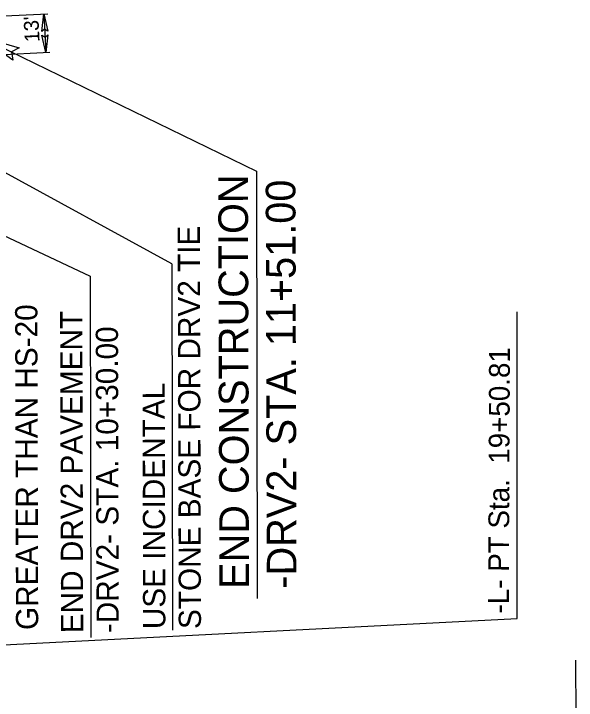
# Model space of a CAD drawing. Extents: x 1373164 to 1374172, y 550391 to 553180.
# Drawn here: x 1373885.8 to 1374075.4, y 551302.8 to 551534.2 of the extents above; entities that cross this region are included whole.
import ezdxf

# ---------------------------------------------------------------- set-up
doc = ezdxf.new("R2010")
doc.units = 0
for name, color, linetype in [('Exist Structure Major Deck Tunnel Box Culvert Cogo Point CELL', 7, 'Continuous'), ('Exist Structure Minor Pipes RCP 18 Inch Cogo Number', 7, 'Continuous'), ('Exist Utilities Sanitary Sewer Manhole Cogo Elevation', 7, 'Continuous')]:
    doc.layers.add(name, color=color, linetype=linetype)

msp = doc.modelspace()

# ---------------------------------------------------------------- linework, layer by layer
at = {"layer": 'Exist Structure Major Deck Tunnel Box Culvert Cogo Point CELL'}
for points in [[(1373895.24, 551528.26), (1373895.95, 551534.15), (1373897.29, 551528.33), (1373896.21, 551529.02)], [(1373885.47, 551518.53), (1373874.34, 551526.52), (1373887.6, 551522.75), (1373885, 551521.34)], [(1373897.32, 551527.06), (1373896.62, 551521.17), (1373895.28, 551526.99), (1373896.36, 551526.3)]]:
    msp.add_lwpolyline(points, close=True, dxfattribs=at)
at = {"layer": 'Exist Structure Minor Pipes RCP 18 Inch Cogo Number'}
for p, q in [((1374055.52, 551330.42), (1374055.43, 551433.73)), ((1373735.63, 551313.89), (1374055.52, 551330.42)), ((1374075.4, 551210.28), (1374075.31, 551316.33))]:
    msp.add_line(p, q, dxfattribs=at)
at = {"layer": 'Exist Utilities Sanitary Sewer Manhole Cogo Elevation'}
for p, q in [((1373874.01, 551533.02), (1373897.27, 551534.22)), ((1373895.95, 551534.15), (1373896.62, 551521.17)), ((1373874.34, 551526.52), (1373967.64, 551481.15)), ((1373874.68, 551520.03), (1373897.94, 551521.24)), ((1373753.5, 551520.28), (1373911.56, 551445.73)), ((1373939.11, 551449.88), (1373817.12, 551516.54)), ((1373967.64, 551481.15), (1373967.84, 551337.11)), ((1373939.11, 551449.88), (1373939.28, 551326.39)), ((1373911.56, 551445.73), (1373911.74, 551323.92))]:
    msp.add_line(p, q, dxfattribs=at)

# ---------------------------------------------------------------- texts
at = {"layer": 'Exist Structure Minor Pipes RCP 18 Inch Cogo Number'}
for s, height, rotation, p in [('END CONSTRUCTION', 10, 90.1567, (1373965.11, 551340.39)), ('-DRV2- STA. 11+51.00', 10, 90.1567, (1373981.11, 551340.44)), ('STONE BASE FOR DRV2 TIE', 7.5, 90.1567, (1373948.92, 551326.83)), ('GREATER THAN HS-20', 7.5, 90.1567, (1373894.06, 551326.5)), ('END DRV2 PAVEMENT', 7.5, 90.1567, (1373909.22, 551325.41)), ('-DRV2- STA. 10+30.00', 7.5, 90.1567, (1373921.22, 551325.45)), ('-L- PT Sta.  19+50.81', 7, 89.7649, (1374052.67, 551332.07)), ('USE INCIDENTAL', 7.5, 90.1567, (1373936.92, 551326.79))]:
    msp.add_text(s, height=height, rotation=rotation, dxfattribs=at).set_placement(p)
at = {"layer": 'Exist Utilities Sanitary Sewer Manhole Cogo Elevation'}
msp.add_text("13'", height=5, rotation=92.9585, dxfattribs=at).set_placement((1373894.53, 551524.77))

doc.saveas('drawing.dxf')
